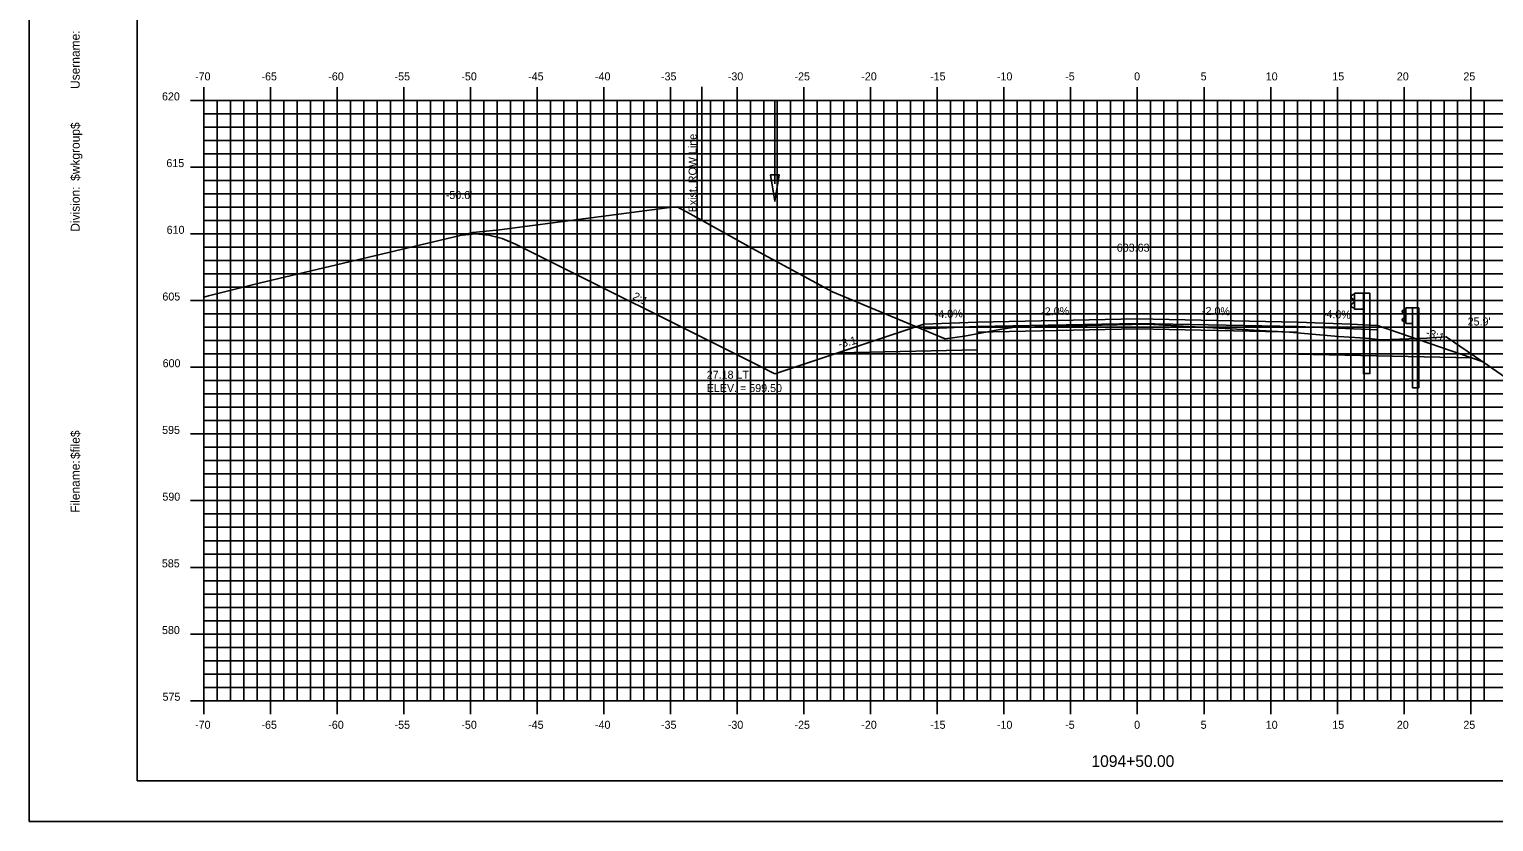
# Model space of a CAD drawing. Extents: x 1074530 to 1074700, y 779716 to 779826.
# Drawn here: x 1074529.6 to 1074639.5, y 779715.6 to 779775 of the extents above; entities that cross this region are included whole.
import ezdxf

# ---------------------------------------------------------------- set-up
doc = ezdxf.new("R2010")
doc.units = 0
for name, color, linetype in [('ANNOTATION', 7, 'Continuous'), ('BORDER', 7, 'Continuous'), ('D_Drainage_Ditch_Line', 7, 'Continuous'), ('D_Guardrail_Beam_Rt', 7, 'Continuous'), ('D_Roadway_Centerline_Text', 7, 'Continuous'), ('D_Roadway_Drive_SubGrade', 7, 'Continuous'), ('D_Roadway_Edge_Pavement', 7, 'Continuous'), ('D_Roadway_Edge_Shoulder', 7, 'Continuous'), ('D_Roadway_Pavement', 7, 'Continuous'), ('D_Roadway_SlopeLines', 7, 'Continuous'), ('D_Roadway_SubGrade', 7, 'Continuous'), ('D_Text_Standard', 7, 'Continuous'), ('E_ROW_Line', 7, 'Continuous'), ('H_V ANNOTATION', 7, 'Continuous'), ('M_Guardrail', 7, 'Continuous'), ('MAJOR', 7, 'Continuous'), ('MINOR', 7, 'Continuous'), ('PLOT BOUNDARY', 7, 'Continuous'), ('S_Guardrail_Beam', 7, 'Continuous'), ('S_Roadway_Centerline', 7, 'Continuous')]:
    doc.layers.add(name, color=color, linetype=linetype)

msp = doc.modelspace()

# ---------------------------------------------------------------- linework, layer by layer
at = {"layer": 'BORDER'}
msp.add_lwpolyline([(1074537.74, 779718.71), (1074697.74, 779718.71), (1074697.74, 779823.71), (1074537.74, 779823.71)], close=True, dxfattribs=at)
at = {"layer": 'D_Drainage_Ditch_Line'}
msp.add_line((1074585.56, 779763.46), (1074585.56, 779769.71), dxfattribs=at)
msp.add_lwpolyline([(1074585.23, 779764.12), (1074585.89, 779764.12), (1074585.56, 779762.15)], close=True, dxfattribs=at)
at = {"layer": 'D_Guardrail_Beam_Rt'}
msp.add_lwpolyline([(1074629.02, 779755.17), (1074628.94, 779755.15), (1074628.92, 779755.15), (1074628.78, 779755.05), (1074628.78, 779754.9), (1074628.97, 779754.77), (1074629.01, 779754.7), (1074629.01, 779754.61), (1074628.97, 779754.55), (1074628.78, 779754.41), (1074628.78, 779754.27), (1074628.92, 779754.17), (1074628.94, 779754.16), (1074629.02, 779754.15)], dxfattribs=at)
for points in [[(1074629.02, 779755.25), (1074629.69, 779755.25), (1074629.69, 779754.07), (1074629.02, 779754.07)], [(1074629.69, 779755.25), (1074630.18, 779755.25), (1074630.18, 779749.24), (1074629.69, 779749.24)]]:
    msp.add_lwpolyline(points, close=True, dxfattribs=at)
at = {"layer": 'D_Roadway_Drive_SubGrade'}
for p, q in [((1074596.74, 779752.93), (1074585.56, 779749.21)), ((1074585.56, 779749.21), (1074584.32, 779749.83))]:
    msp.add_line(p, q, dxfattribs=at)
at = {"layer": 'D_Roadway_Edge_Pavement'}
msp.add_lwpolyline([(1074600.74, 779752.76), (1074600.74, 779753.09), (1074612.74, 779753.33), (1074624.74, 779753.09), (1074624.74, 779752.76), (1074612.74, 779753)], close=True, dxfattribs=at)
at = {"layer": 'D_Roadway_Edge_Shoulder'}
msp.add_lwpolyline([(1074600.74, 779753.09), (1074596.74, 779752.93), (1074596.74, 779752.6), (1074600.74, 779752.76)], close=True, dxfattribs=at)
msp.add_lwpolyline([(1074624.74, 779753.09), (1074628.74, 779752.93), (1074630.74, 779752.85), (1074630.74, 779752.52), (1074624.74, 779752.76), (1074624.74, 779753.09)], dxfattribs=at)
at = {"layer": 'D_Roadway_Pavement'}
msp.add_lwpolyline([(1074600.74, 779752.34), (1074600.74, 779752.76), (1074612.74, 779753), (1074624.74, 779752.76), (1074624.74, 779752.34), (1074612.74, 779752.58)], close=True, dxfattribs=at)
msp.add_lwpolyline([(1074600.74, 779752.76), (1074600.74, 779752.34)], dxfattribs=at)
at = {"layer": 'D_Roadway_SlopeLines'}
for points in [[(1074584.32, 779749.83), (1074566.1, 779758.93), (1074565.1, 779759.35), (1074564.1, 779759.61), (1074563.1, 779759.7), (1074562.11, 779759.62)], [(1074600.74, 779753.09), (1074596.74, 779752.93)], [(1074630.74, 779752.85), (1074637.81, 779750.42), (1074638.6, 779750.14)]]:
    msp.add_lwpolyline(points, dxfattribs=at)
at = {"layer": 'D_Roadway_SubGrade'}
for points in [[(1074590.35, 779750.8), (1074600.74, 779751.01), (1074600.74, 779752.76), (1074596.74, 779752.6), (1074596.74, 779752.93)], [(1074637.81, 779750.42), (1074624.74, 779750.68), (1074624.74, 779751.26), (1074624.74, 779752.76), (1074624.74, 779752.76), (1074630.74, 779752.52), (1074630.74, 779752.85)]]:
    msp.add_lwpolyline(points, dxfattribs=at)
at = {"layer": 'E_ROW_Line'}
msp.add_line((1074580.09, 779760.72), (1074580.09, 779770.72), dxfattribs=at)
msp.add_line((1074580.09, 779760.72), (1074580.09, 779770.72), dxfattribs=at)
at = {"layer": 'M_Guardrail'}
for p, q in [((1074633.37, 779754.16), (1074633.86, 779754.16)), ((1074633.86, 779754.16), (1074633.86, 779748.16)), ((1074633.37, 779748.16), (1074633.37, 779752.99)), ((1074633.37, 779748.16), (1074633.86, 779748.16))]:
    msp.add_line(p, q, dxfattribs=at)
at = {"layer": 'MAJOR'}
for p, q in [((1074542.74, 779770.71), (1074542.74, 779769.71)), ((1074547.74, 779770.71), (1074547.74, 779769.71)), ((1074552.74, 779770.71), (1074552.74, 779769.71)), ((1074557.74, 779770.71), (1074557.74, 779769.71)), ((1074562.74, 779770.71), (1074562.74, 779769.71)), ((1074567.74, 779770.71), (1074567.74, 779769.71)), ((1074572.74, 779770.71), (1074572.74, 779769.71)), ((1074577.74, 779770.71), (1074577.74, 779769.71)), ((1074582.74, 779770.71), (1074582.74, 779769.71)), ((1074587.74, 779770.71), (1074587.74, 779769.71)), ((1074592.74, 779770.71), (1074592.74, 779769.71)), ((1074597.74, 779770.71), (1074597.74, 779769.71)), ((1074602.74, 779770.71), (1074602.74, 779769.71)), ((1074607.74, 779770.71), (1074607.74, 779769.71)), ((1074612.74, 779770.71), (1074612.74, 779769.71)), ((1074617.74, 779770.71), (1074617.74, 779769.71)), ((1074622.74, 779770.71), (1074622.74, 779769.71)), ((1074627.74, 779770.71), (1074627.74, 779769.71)), ((1074632.74, 779770.71), (1074632.74, 779769.71)), ((1074637.74, 779770.71), (1074637.74, 779769.71)), ((1074541.74, 779769.71), (1074542.74, 779769.71)), ((1074542.74, 779769.71), (1074682.74, 779769.71)), ((1074542.74, 779724.71), (1074542.74, 779769.71)), ((1074542.74, 779724.71), (1074542.74, 779769.71)), ((1074542.74, 779769.71), (1074682.74, 779769.71)), ((1074547.74, 779724.71), (1074547.74, 779769.71)), ((1074552.74, 779724.71), (1074552.74, 779769.71)), ((1074557.74, 779724.71), (1074557.74, 779769.71)), ((1074562.74, 779724.71), (1074562.74, 779769.71)), ((1074567.74, 779724.71), (1074567.74, 779769.71)), ((1074572.74, 779724.71), (1074572.74, 779769.71)), ((1074577.74, 779724.71), (1074577.74, 779769.71)), ((1074582.74, 779724.71), (1074582.74, 779769.71)), ((1074587.74, 779724.71), (1074587.74, 779769.71)), ((1074592.74, 779724.71), (1074592.74, 779769.71)), ((1074597.74, 779724.71), (1074597.74, 779769.71)), ((1074602.74, 779724.71), (1074602.74, 779769.71)), ((1074607.74, 779724.71), (1074607.74, 779769.71)), ((1074612.74, 779724.71), (1074612.74, 779769.71)), ((1074617.74, 779724.71), (1074617.74, 779769.71)), ((1074622.74, 779724.71), (1074622.74, 779769.71)), ((1074627.74, 779724.71), (1074627.74, 779769.71)), ((1074632.74, 779724.71), (1074632.74, 779769.71)), ((1074637.74, 779724.71), (1074637.74, 779769.71)), ((1074541.74, 779764.71), (1074542.74, 779764.71)), ((1074542.74, 779764.71), (1074682.74, 779764.71)), ((1074541.74, 779759.71), (1074542.74, 779759.71)), ((1074542.74, 779759.71), (1074682.74, 779759.71)), ((1074541.74, 779754.71), (1074542.74, 779754.71)), ((1074542.74, 779754.71), (1074682.74, 779754.71)), ((1074541.74, 779749.71), (1074542.74, 779749.71)), ((1074542.74, 779749.71), (1074682.74, 779749.71)), ((1074541.74, 779744.71), (1074542.74, 779744.71)), ((1074542.74, 779744.71), (1074682.74, 779744.71)), ((1074541.74, 779739.71), (1074542.74, 779739.71)), ((1074542.74, 779739.71), (1074682.74, 779739.71)), ((1074541.74, 779734.71), (1074542.74, 779734.71)), ((1074542.74, 779734.71), (1074682.74, 779734.71)), ((1074541.74, 779729.71), (1074542.74, 779729.71)), ((1074542.74, 779729.71), (1074682.74, 779729.71)), ((1074541.74, 779724.71), (1074542.74, 779724.71)), ((1074542.74, 779724.71), (1074682.74, 779724.71)), ((1074542.74, 779724.71), (1074682.74, 779724.71)), ((1074542.74, 779723.7), (1074542.74, 779724.71)), ((1074547.74, 779723.7), (1074547.74, 779724.71)), ((1074552.74, 779723.7), (1074552.74, 779724.71)), ((1074557.74, 779723.7), (1074557.74, 779724.71)), ((1074562.74, 779723.7), (1074562.74, 779724.71)), ((1074567.74, 779723.7), (1074567.74, 779724.71)), ((1074572.74, 779723.7), (1074572.74, 779724.71)), ((1074577.74, 779723.7), (1074577.74, 779724.71)), ((1074582.74, 779723.7), (1074582.74, 779724.71)), ((1074587.74, 779723.7), (1074587.74, 779724.71)), ((1074592.74, 779723.7), (1074592.74, 779724.71)), ((1074597.74, 779723.7), (1074597.74, 779724.71)), ((1074602.74, 779723.7), (1074602.74, 779724.71)), ((1074607.74, 779723.7), (1074607.74, 779724.71)), ((1074612.74, 779723.7), (1074612.74, 779724.71)), ((1074617.74, 779723.7), (1074617.74, 779724.71)), ((1074622.74, 779723.7), (1074622.74, 779724.71)), ((1074627.74, 779723.7), (1074627.74, 779724.71)), ((1074632.74, 779723.7), (1074632.74, 779724.71)), ((1074637.74, 779723.7), (1074637.74, 779724.71))]:
    msp.add_line(p, q, dxfattribs=at)
at = {"layer": 'MINOR'}
for p, q in [((1074543.74, 779724.71), (1074543.74, 779769.71)), ((1074544.74, 779724.71), (1074544.74, 779769.71)), ((1074545.74, 779724.71), (1074545.74, 779769.71)), ((1074546.74, 779724.71), (1074546.74, 779769.71)), ((1074548.74, 779724.71), (1074548.74, 779769.71)), ((1074549.74, 779724.71), (1074549.74, 779769.71)), ((1074550.74, 779724.71), (1074550.74, 779769.71)), ((1074551.74, 779724.71), (1074551.74, 779769.71)), ((1074553.74, 779724.71), (1074553.74, 779769.71)), ((1074554.74, 779724.71), (1074554.74, 779769.71)), ((1074555.74, 779724.71), (1074555.74, 779769.71)), ((1074556.74, 779724.71), (1074556.74, 779769.71)), ((1074558.74, 779724.71), (1074558.74, 779769.71)), ((1074559.74, 779724.71), (1074559.74, 779769.71)), ((1074560.74, 779724.71), (1074560.74, 779769.71)), ((1074561.74, 779724.71), (1074561.74, 779769.71)), ((1074563.74, 779724.71), (1074563.74, 779769.71)), ((1074564.74, 779724.71), (1074564.74, 779769.71)), ((1074565.74, 779724.71), (1074565.74, 779769.71)), ((1074566.74, 779724.71), (1074566.74, 779769.71)), ((1074568.74, 779724.71), (1074568.74, 779769.71)), ((1074569.74, 779724.71), (1074569.74, 779769.71)), ((1074570.74, 779724.71), (1074570.74, 779769.71)), ((1074571.74, 779724.71), (1074571.74, 779769.71)), ((1074573.74, 779724.71), (1074573.74, 779769.71)), ((1074574.74, 779724.71), (1074574.74, 779769.71)), ((1074575.74, 779724.71), (1074575.74, 779769.71)), ((1074576.74, 779724.71), (1074576.74, 779769.71)), ((1074578.74, 779724.71), (1074578.74, 779769.71)), ((1074579.74, 779724.71), (1074579.74, 779769.71)), ((1074580.74, 779724.71), (1074580.74, 779769.71)), ((1074581.74, 779724.71), (1074581.74, 779769.71)), ((1074583.74, 779724.71), (1074583.74, 779769.71)), ((1074584.74, 779724.71), (1074584.74, 779769.71)), ((1074585.74, 779724.71), (1074585.74, 779769.71)), ((1074586.74, 779724.71), (1074586.74, 779769.71)), ((1074588.74, 779724.71), (1074588.74, 779769.71)), ((1074589.74, 779724.71), (1074589.74, 779769.71)), ((1074590.74, 779724.71), (1074590.74, 779769.71)), ((1074591.74, 779724.71), (1074591.74, 779769.71)), ((1074593.74, 779724.71), (1074593.74, 779769.71)), ((1074594.74, 779724.71), (1074594.74, 779769.71)), ((1074595.74, 779724.71), (1074595.74, 779769.71)), ((1074596.74, 779724.71), (1074596.74, 779769.71)), ((1074598.74, 779724.71), (1074598.74, 779769.71)), ((1074599.74, 779724.71), (1074599.74, 779769.71)), ((1074600.74, 779724.71), (1074600.74, 779769.71)), ((1074601.74, 779724.71), (1074601.74, 779769.71)), ((1074603.74, 779724.71), (1074603.74, 779769.71)), ((1074604.74, 779724.71), (1074604.74, 779769.71)), ((1074605.74, 779724.71), (1074605.74, 779769.71)), ((1074606.74, 779724.71), (1074606.74, 779769.71)), ((1074608.74, 779724.71), (1074608.74, 779769.71)), ((1074609.74, 779724.71), (1074609.74, 779769.71)), ((1074610.74, 779724.71), (1074610.74, 779769.71)), ((1074611.74, 779724.71), (1074611.74, 779769.71)), ((1074613.74, 779724.71), (1074613.74, 779769.71)), ((1074614.74, 779724.71), (1074614.74, 779769.71)), ((1074615.74, 779724.71), (1074615.74, 779769.71)), ((1074616.74, 779724.71), (1074616.74, 779769.71)), ((1074618.74, 779724.71), (1074618.74, 779769.71)), ((1074619.74, 779724.71), (1074619.74, 779769.71)), ((1074620.74, 779724.71), (1074620.74, 779769.71)), ((1074621.74, 779724.71), (1074621.74, 779769.71)), ((1074623.74, 779724.71), (1074623.74, 779769.71)), ((1074624.74, 779724.71), (1074624.74, 779769.71)), ((1074625.74, 779724.71), (1074625.74, 779769.71)), ((1074626.74, 779724.71), (1074626.74, 779769.71)), ((1074628.74, 779724.71), (1074628.74, 779769.71)), ((1074629.74, 779724.71), (1074629.74, 779769.71)), ((1074630.74, 779724.71), (1074630.74, 779769.71)), ((1074631.74, 779724.71), (1074631.74, 779769.71)), ((1074633.74, 779724.71), (1074633.74, 779769.71)), ((1074634.74, 779724.71), (1074634.74, 779769.71)), ((1074635.74, 779724.71), (1074635.74, 779769.71)), ((1074636.74, 779724.71), (1074636.74, 779769.71)), ((1074638.74, 779724.71), (1074638.74, 779769.71)), ((1074542.74, 779768.71), (1074682.74, 779768.71)), ((1074542.74, 779768.71), (1074543.74, 779768.71)), ((1074542.74, 779767.71), (1074682.74, 779767.71)), ((1074542.74, 779767.71), (1074543.74, 779767.71)), ((1074542.74, 779766.71), (1074682.74, 779766.71)), ((1074542.74, 779766.71), (1074543.74, 779766.71)), ((1074542.74, 779765.71), (1074682.74, 779765.71)), ((1074542.74, 779765.71), (1074543.74, 779765.71)), ((1074542.74, 779763.71), (1074682.74, 779763.71)), ((1074542.74, 779763.71), (1074543.74, 779763.71)), ((1074542.74, 779762.71), (1074682.74, 779762.71)), ((1074542.74, 779762.71), (1074543.74, 779762.71)), ((1074542.74, 779761.71), (1074682.74, 779761.71)), ((1074542.74, 779761.71), (1074543.74, 779761.71)), ((1074542.74, 779760.71), (1074682.74, 779760.71)), ((1074542.74, 779760.71), (1074543.74, 779760.71)), ((1074542.74, 779758.71), (1074682.74, 779758.71)), ((1074542.74, 779758.71), (1074543.74, 779758.71)), ((1074542.74, 779757.71), (1074682.74, 779757.71)), ((1074542.74, 779757.71), (1074543.74, 779757.71)), ((1074542.74, 779756.71), (1074682.74, 779756.71)), ((1074542.74, 779756.71), (1074543.74, 779756.71)), ((1074542.74, 779755.71), (1074682.74, 779755.71)), ((1074542.74, 779755.71), (1074543.74, 779755.71)), ((1074542.74, 779753.71), (1074682.74, 779753.71)), ((1074542.74, 779753.71), (1074543.74, 779753.71)), ((1074542.74, 779752.71), (1074682.74, 779752.71)), ((1074542.74, 779752.71), (1074543.74, 779752.71)), ((1074542.74, 779751.71), (1074682.74, 779751.71)), ((1074542.74, 779751.71), (1074543.74, 779751.71)), ((1074542.74, 779750.71), (1074682.74, 779750.71)), ((1074542.74, 779750.71), (1074543.74, 779750.71)), ((1074542.74, 779748.71), (1074682.74, 779748.71)), ((1074542.74, 779748.71), (1074543.74, 779748.71)), ((1074542.74, 779747.71), (1074682.74, 779747.71)), ((1074542.74, 779747.71), (1074543.74, 779747.71)), ((1074542.74, 779746.71), (1074682.74, 779746.71)), ((1074542.74, 779746.71), (1074543.74, 779746.71)), ((1074542.74, 779745.71), (1074682.74, 779745.71)), ((1074542.74, 779745.71), (1074543.74, 779745.71)), ((1074542.74, 779743.71), (1074682.74, 779743.71)), ((1074542.74, 779743.71), (1074543.74, 779743.71)), ((1074542.74, 779742.71), (1074682.74, 779742.71)), ((1074542.74, 779742.71), (1074543.74, 779742.71)), ((1074542.74, 779741.71), (1074682.74, 779741.71)), ((1074542.74, 779741.71), (1074543.74, 779741.71)), ((1074542.74, 779740.71), (1074682.74, 779740.71)), ((1074542.74, 779740.71), (1074543.74, 779740.71)), ((1074542.74, 779738.71), (1074682.74, 779738.71)), ((1074542.74, 779738.71), (1074543.74, 779738.71)), ((1074542.74, 779737.71), (1074682.74, 779737.71)), ((1074542.74, 779737.71), (1074543.74, 779737.71)), ((1074542.74, 779736.71), (1074682.74, 779736.71)), ((1074542.74, 779736.71), (1074543.74, 779736.71)), ((1074542.74, 779735.71), (1074682.74, 779735.71)), ((1074542.74, 779735.71), (1074543.74, 779735.71)), ((1074542.74, 779733.71), (1074682.74, 779733.71)), ((1074542.74, 779733.71), (1074543.74, 779733.71)), ((1074542.74, 779732.71), (1074682.74, 779732.71)), ((1074542.74, 779732.71), (1074543.74, 779732.71)), ((1074542.74, 779731.71), (1074682.74, 779731.71)), ((1074542.74, 779731.71), (1074543.74, 779731.71)), ((1074542.74, 779730.71), (1074682.74, 779730.71)), ((1074542.74, 779730.71), (1074543.74, 779730.71)), ((1074542.74, 779728.71), (1074682.74, 779728.71)), ((1074542.74, 779728.71), (1074543.74, 779728.71)), ((1074542.74, 779727.71), (1074682.74, 779727.71)), ((1074542.74, 779727.71), (1074543.74, 779727.71)), ((1074542.74, 779726.71), (1074682.74, 779726.71)), ((1074542.74, 779726.71), (1074543.74, 779726.71)), ((1074542.74, 779725.71), (1074682.74, 779725.71)), ((1074542.74, 779725.71), (1074543.74, 779725.71))]:
    msp.add_line(p, q, dxfattribs=at)
at = {"layer": 'PLOT BOUNDARY'}
msp.add_lwpolyline([(1074529.65, 779715.65), (1074699.65, 779715.65), (1074699.65, 779825.65), (1074529.65, 779825.65)], close=True, dxfattribs=at)
at = {"layer": 'S_Guardrail_Beam'}
for p, q in [((1074632.78, 779754.06), (1074632.64, 779753.96)), ((1074632.64, 779753.82), (1074632.83, 779753.68)), ((1074632.88, 779754.08), (1074632.8, 779754.07)), ((1074632.88, 779754.16), (1074633.37, 779754.16)), ((1074632.88, 779752.99), (1074632.88, 779754.16)), ((1074633.37, 779754.16), (1074633.37, 779752.99)), ((1074632.83, 779753.46), (1074632.64, 779753.33)), ((1074632.64, 779753.18), (1074632.78, 779753.08)), ((1074632.8, 779753.08), (1074632.88, 779753.06)), ((1074632.87, 779753.62), (1074632.87, 779753.53)), ((1074633.37, 779752.99), (1074632.88, 779752.99))]:
    msp.add_line(p, q, dxfattribs=at)
for centre, major_axis, start_param, end_param in [((1074632.69, 779753.89), (-0.0877, 0), 5.323254, 7.243116), ((1074632.81, 779754.03), (-0.0417, 0), 4.886922, 5.323254), ((1074632.79, 779753.62), (0.0789, 0), 0, 0.959931), ((1074632.69, 779753.26), (-0.0877, 0), 5.323254, 7.243116), ((1074632.81, 779753.12), (-0.0417, 0), 0.959931, 1.396263), ((1074632.79, 779753.53), (0.0789, 0), 5.323254, 6.283185)]:
    msp.add_ellipse(centre, major_axis=major_axis, ratio=0.995501, start_param=start_param, end_param=end_param, dxfattribs=at)
at = {"layer": 'S_Roadway_Centerline'}
msp.add_lwpolyline([(1074542.74, 779754.97), (1074543.08, 779755.06), (1074546.89, 779756.01), (1074562.9, 779759.81), (1074564.92, 779760.01), (1074577.86, 779761.7), (1074578.24, 779761.73), (1074579.2, 779761.21), (1074583.84, 779758.63), (1074589.89, 779755.36), (1074598.33, 779751.83), (1074599.78, 779752.03), (1074602.44, 779752.54), (1074603.39, 779752.69), (1074606.73, 779752.79), (1074613.49, 779752.93), (1074618.87, 779752.65), (1074624.14, 779752.35), (1074627.83, 779752.02), (1074629.84, 779751.9), (1074631.04, 779751.76), (1074634.46, 779751.89), (1074635.9, 779751.98), (1074639.06, 779749.83), (1074649.68, 779742.5)], dxfattribs=at)

# ---------------------------------------------------------------- texts
at = {"layer": 'ANNOTATION'}
for s, rotation, p in [('2:1', 333.4349, (1074574.84, 779754.84)), ('-4.0%', 2.2906, (1074597.56, 779753.37)), ('-2.0%', 1.1458, (1074605.54, 779753.59)), ('-2.0%', 358.8542, (1074617.58, 779753.64)), ('-4.0%', 357.7094, (1074626.64, 779753.42)), ('-3:1', 14.0362, (1074590.39, 779751.14)), ('-3:1', 340.9744, (1074634.33, 779752.07))]:
    msp.add_text(s, height=0.6, rotation=rotation, dxfattribs=at).set_placement(p)
for s, p in [('27.18 LT', (1074580.45, 779748.85)), ('ELEV. = 599.50', (1074580.45, 779747.85))]:
    msp.add_text(s, height=0.6, dxfattribs=at).set_placement(p)
at = {"layer": 'BORDER'}
for s, p in [('Username:', (1074533.43, 779770.57)), ('$wkgroup$', (1074533.43, 779763.68)), ('Division:', (1074533.43, 779759.87)), ('$file$', (1074533.43, 779742.83)), ('Filename:', (1074533.43, 779738.8))]:
    msp.add_text(s, height=0.67, rotation=90, dxfattribs=at).set_placement(p)
at = {"layer": 'D_Roadway_Centerline_Text'}
msp.add_text('603.63', height=0.6, dxfattribs=at).set_placement((1074611.2, 779758.37))
at = {"layer": 'D_Text_Standard'}
for s, p in [("-50.6'", (1074560.88, 779762.32)), ("25.9'", (1074637.51, 779752.84))]:
    msp.add_text(s, height=0.6, dxfattribs=at).set_placement(p)
at = {"layer": 'E_ROW_Line'}
msp.add_text('Exist. ROW Line', height=0.6, rotation=90, dxfattribs=at).set_placement((1074579.69, 779761.32))
at = {"layer": 'H_V ANNOTATION'}
for s, height, p in [('-70', 0.6, (1074542.08, 779771.21)), ('-65', 0.6, (1074547.06, 779771.21)), ('-60', 0.6, (1074552.07, 779771.21)), ('-55', 0.6, (1074557.04, 779771.21)), ('-50', 0.6, (1074562.05, 779771.21)), ('-45', 0.6, (1074567.06, 779771.21)), ('-40', 0.6, (1074572.07, 779771.21)), ('-35', 0.6, (1074577.02, 779771.21)), ('-30', 0.6, (1074582.03, 779771.21)), ('-25', 0.6, (1074587.03, 779771.21)), ('-20', 0.6, (1074592.04, 779771.21)), ('-15', 0.6, (1074597.2, 779771.21)), ('-10', 0.6, (1074602.21, 779771.21)), ('-5', 0.6, (1074607.33, 779771.21)), ('0', 0.6, (1074612.5, 779771.21)), ('5', 0.6, (1074617.49, 779771.21)), ('10', 0.6, (1074622.37, 779771.21)), ('15', 0.6, (1074627.36, 779771.21)), ('20', 0.6, (1074632.2, 779771.21)), ('25', 0.6, (1074637.19, 779771.21)), ('620', 0.6, (1074539.6, 779769.71)), ('615', 0.6, (1074539.93, 779764.71)), ('610', 0.6, (1074539.95, 779759.71)), ('605', 0.6, (1074539.63, 779754.71)), ('600', 0.6, (1074539.65, 779749.71)), ('595', 0.6, (1074539.61, 779744.71)), ('590', 0.6, (1074539.63, 779739.71)), ('585', 0.6, (1074539.59, 779734.71)), ('580', 0.6, (1074539.6, 779729.71)), ('575', 0.6, (1074539.64, 779724.71)), ('-70', 0.6, (1074542.08, 779722.61)), ('-65', 0.6, (1074547.06, 779722.61)), ('-60', 0.6, (1074552.07, 779722.61)), ('-55', 0.6, (1074557.04, 779722.61)), ('-50', 0.6, (1074562.05, 779722.61)), ('-45', 0.6, (1074567.06, 779722.61)), ('-40', 0.6, (1074572.07, 779722.61)), ('-35', 0.6, (1074577.02, 779722.61)), ('-30', 0.6, (1074582.03, 779722.61)), ('-25', 0.6, (1074587.03, 779722.61)), ('-20', 0.6, (1074592.04, 779722.61)), ('-15', 0.6, (1074597.2, 779722.61)), ('-10', 0.6, (1074602.21, 779722.61)), ('-5', 0.6, (1074607.33, 779722.61)), ('0', 0.6, (1074612.5, 779722.61)), ('5', 0.6, (1074617.49, 779722.61)), ('10', 0.6, (1074622.37, 779722.61)), ('15', 0.6, (1074627.36, 779722.61)), ('20', 0.6, (1074632.2, 779722.61)), ('25', 0.6, (1074637.19, 779722.61)), ('1094+50.00', 0.875, (1074609.3, 779719.75))]:
    msp.add_text(s, height=height, dxfattribs=at).set_placement(p)
at = {"layer": 'MAJOR'}
msp.add_text('-', height=0.006, dxfattribs=at).set_placement((1074542.74, 779724.71))

doc.saveas('drawing.dxf')
